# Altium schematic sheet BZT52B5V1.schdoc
size 127 x 101 mm
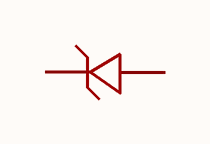
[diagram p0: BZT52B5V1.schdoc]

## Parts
D?  bzt52b5v1_c78479  [SOD-123_L2.8-W1.8-LS3.7-RD]  (value not drawn)

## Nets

Not connected (* = marked no-connect by the designer): D? 1(K) 2(A)

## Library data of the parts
D? = bzt52b5v1_c78479: 二极管配置:1个独立式;稳压值(标称值):5.1V;稳压值(范围值):5V~5.2V;耗散功率(Pd):350mW;; Manufacturer: CJ(江苏长电/长晶); AddInBom: yes; ModelId: 7884390a25fb4c08947731ebfba7e3f8; ModelTransform: 144.8816,62.992,0,0,0,0,0,0,0; Diode Configuration: 1个独立式; Zener Voltage(Nom): 5.1V; Reverse Leakage Current (Ir): 2uA; Pd - Power Dissipation: 350mW; Impedance(Zzt): 60Ω; Impedance(Zzk): 480Ω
